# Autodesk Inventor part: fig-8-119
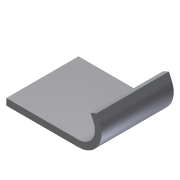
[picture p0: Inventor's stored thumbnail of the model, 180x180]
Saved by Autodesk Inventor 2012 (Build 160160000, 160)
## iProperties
Created: 2009-09
Part Number: fig-8-119
Document SubType Name: Modeling
Designer: Sham
Density: 1 g/cm^3
Material: Default
Author: Sham
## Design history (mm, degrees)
sketch "Sketch1"
  geometry: L1 (-33.976, 22)-(0, 22); L2 (0, 22)-(0, 0); L3 (0, 0)-(-33.976, 0); L4 (-33.976, 0)-(-33.976, 22)
  constraints: 8 end point, 2 parallel, 1 horizontal, 1 perpendicular
extrude "Extrusion1" new body sketch "Sketch1" distance "d0" = 2; taper "d1" = 0 deg
sketch "Sketch2"
  geometry: L1 (-12, 22)-(-12, 0)
  constraints: 2 end point
feature "Bend Part1" sketch "Sketch2" dims "d2" = 5, "d4" = 10
body "Solid1"
